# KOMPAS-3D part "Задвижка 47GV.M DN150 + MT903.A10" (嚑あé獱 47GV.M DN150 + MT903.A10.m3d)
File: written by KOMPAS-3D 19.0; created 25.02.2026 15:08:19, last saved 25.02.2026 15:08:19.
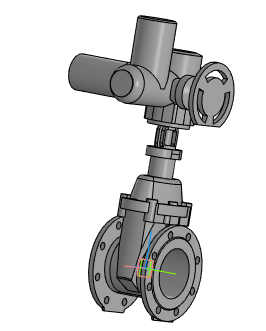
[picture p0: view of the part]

Document properties: Автор: Энергия; Полное имя файла: 47GV.M DN150\Задвижка 47GV.M DN150 с маховиком.a3d

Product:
- Part/product: Задвижка 47GV.M DN150 + MT903.A10
    Масса: 130.655
  - Component: Задвижка с обрезиненным клином DN125. Сборочный чертеж  | designation DR.47GVM.125.16.00.00СБ  | pos. 0  | Масса: 25.3494; Раздел спецификации: Документация; Форматы листов документа: 2xA3; source file: 47GV.M DN150\DR.47GVM.125.16.00.000 СБ - Задвижка с обрезиненным клином DN125.cdw

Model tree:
1. Операция без истории:1

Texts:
  Точка начала. Х
  Точка начала. Y
  Точка начала. Z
